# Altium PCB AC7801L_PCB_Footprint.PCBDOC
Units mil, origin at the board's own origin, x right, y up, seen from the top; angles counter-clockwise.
Board outline 634.92 x 634.92 mil, 2 copper layers (Top, Bottom), stack 12.7 mil thick; 1 components, 0 nets, 49 pads, 0 vias.
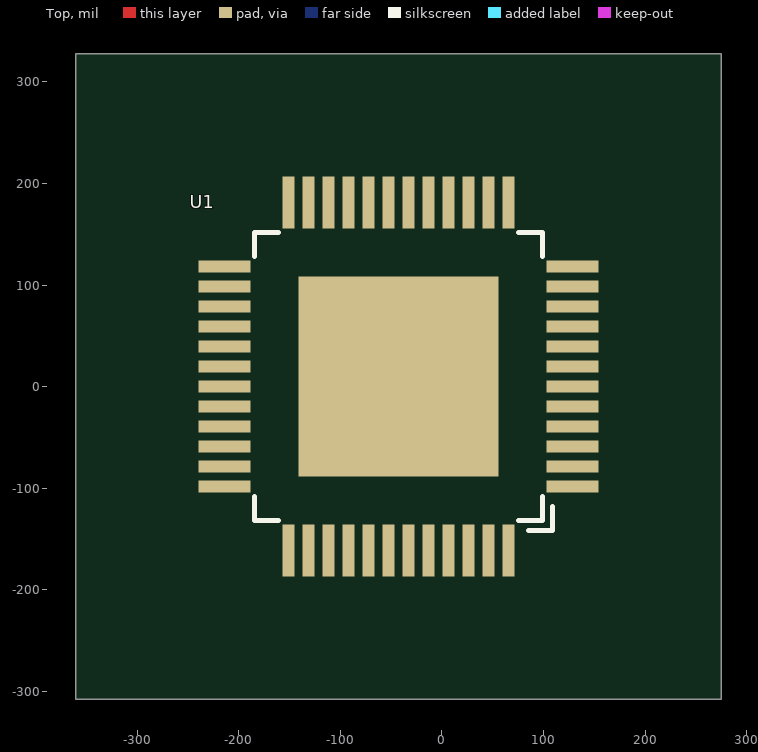
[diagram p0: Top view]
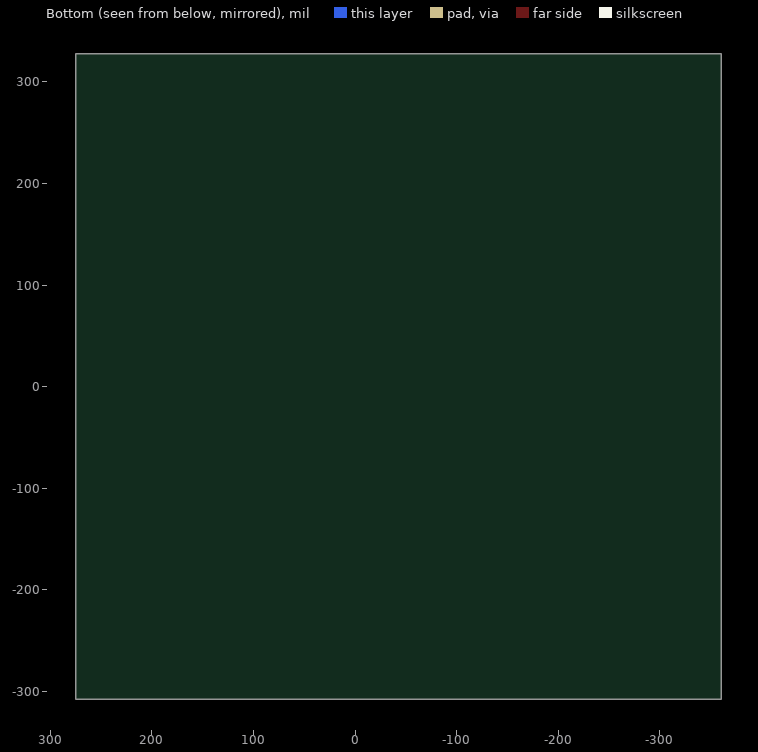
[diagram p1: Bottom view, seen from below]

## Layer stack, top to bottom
Top: signal copper 1.35
Dielectric: dielectric 10, FR-4, Dk 4.3
Bottom: signal copper 1.35

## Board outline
-360.21,-307.37 274.71,-307.37 274.71,327.55 -360.21,327.55

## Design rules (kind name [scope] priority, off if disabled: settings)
Clearance "'Default' PADS rule_18" [All] p1: gap=6
Clearance "'Default' PADS rule_15" [IsVia vs IsVia] p2: gap=6
ComponentClearance "'Default' PADS rule_12" [All] p1: gap=6 collisioncheckmode=3 verticalgap=10 showdistances=FALSE
FlightTimeFalling "'Default' PADS rule_10" [All] p1: maximum=10.00
FlightTimeRising "'Default' PADS rule_9" [All] p1: maximum=10.00
Length "'Default' PADS rule_5" [All] p1: maxlimit=50000 minlimit=0
MatchedLengths "'Default' PADS rule_11" [InNetClass('All Nets')] p1: tolerance=200 checknetsindiffpair=TRUE checkdiffpairvsdiffpair=TRUE checkothers=TRUE
MaxMinImpedance "'Default' PADS rule_8" [All] p1: minimum=50.00 maximum=150.0
ParallelSegment "'Default' PADS rule_7" [All] p1: limit=1000 gap=200
ParallelSegment "'Default' PADS rule_6" [All] p2: limit=1000 gap=200
PlaneClearance "'Default' PADS rule_14" [All] p1: clearance=6
PlaneConnect "Power Plane Connect Style - from global settings" [All] p1: planeconnectstyle=Relief reliefexpansion=20 reliefentries=2 reliefconductorwidth=15 reliefairgap=10
PolygonConnect [All] p1: connectstyle=Relief reliefconductorwidth=10 reliefentries=4 polygonreliefangle="90 Angle"
RoutingLayers "'Default' PADS rule_3" [All] p1: top layer_v5=TRUE bottom layer_v5=TRUE
RoutingPriority "'Default' PADS rule_2" [All] p1: routingpriority=3
RoutingTopology "'Default' PADS rule" [All] p1: topology=Shortest
RoutingVias "'Default' PADS rule_4" [All] p1: holewidth=37 width=55 viastyle="Through Hole" minholewidth=37 minwidth=55 maxholewidth=37 maxwidth=55
SMDToCorner "'Default' PADS rule_16" [All] p1: distance=60000
SMDToPlane "'Default' PADS rule_17" [All] p1: distance=60000
SilkscreenOverComponentPads [All] p1: minsilkscreentomaskgap=10
SolderMaskExpansion [All] p1: expansion=4
TestPointUsage [All] p1: valid=0 allowmultiple=FALSE
Testpoint [All] p1: side=15 testpointundercomponent=TRUE minsize=40 maxsize=100 preferedsize=60 minholesize=0 maxholesize=40 preferedholesize=32 testpointgrid=1 style=1023 order=0-112345678
Width "'Default' PADS rule_13" [All] p1: maxlimit=12 minlimit=12 preferedwidth=12
17 further rules are at their usual default settings.

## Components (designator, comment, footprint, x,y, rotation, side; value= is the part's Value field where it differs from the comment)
U1 "AC79013FDLA/LQFP48/SMD/P0.5/7X7" AC79013FDLA/LQFP48/SMD/P0.5/7X7 -42.75,10.09 r90 top

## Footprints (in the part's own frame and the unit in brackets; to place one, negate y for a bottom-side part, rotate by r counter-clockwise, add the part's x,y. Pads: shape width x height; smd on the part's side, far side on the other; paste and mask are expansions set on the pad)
AC79013FDLA/LQFP48/SMD/P0.5/7X7 [mm]
  rect 0.3x1.3 smd: 1(-2.75,-4.35) 2(-2.25,-4.35) 3(-1.75,-4.35) 4(-1.25,-4.35) 5(-0.75,-4.35) 6(-0.25,-4.35) 7(0.25,-4.35) 8(0.75,-4.35) 9(1.25,-4.35) 10(1.75,-4.35) 11(2.25,-4.35) 12(2.75,-4.35) 25(2.75,4.35) 26(2.25,4.35) 27(1.75,4.35) 28(1.25,4.35) 29(0.75,4.35) 30(0.25,4.35) 31(-0.25,4.35) 32(-0.75,4.35) 33(-1.25,4.35) 34(-1.75,4.35) 35(-2.25,4.35) 36(-2.75,4.35)
  rect 1.3x0.3 smd: 13(4.35,-2.75) 14(4.35,-2.25) 15(4.35,-1.75) 16(4.35,-1.25) 17(4.35,-0.75) 18(4.35,-0.25) 19(4.35,0.25) 20(4.35,0.75) 21(4.35,1.25) 22(4.35,1.75) 23(4.35,2.25) 24(4.35,2.75) 37(-4.35,2.75) 38(-4.35,2.25) 39(-4.35,1.75) 40(-4.35,1.25) 41(-4.35,0.75) 42(-4.35,0.25) 43(-4.35,-0.25) 44(-4.35,-0.75) 45(-4.35,-1.25) 46(-4.35,-1.75) 47(-4.35,-2.25) 48(-4.35,-2.75)
  rect 5x5 smd: 49(0,0)
  silkscreen extent -3.85,-3.85 3.6,3.6

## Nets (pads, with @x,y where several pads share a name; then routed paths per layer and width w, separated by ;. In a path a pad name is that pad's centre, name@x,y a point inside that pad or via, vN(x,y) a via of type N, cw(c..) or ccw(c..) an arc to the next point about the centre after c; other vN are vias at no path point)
pads on no net: U1.1 U1.2 U1.3 U1.4 U1.5 U1.6 U1.7 U1.8 U1.9 U1.10 U1.11 U1.12 U1.13 U1.14 U1.15 U1.16 U1.17 U1.18 U1.19 U1.20 U1.21 U1.22 U1.23 U1.24 U1.25 U1.26 U1.27 U1.28 U1.29 U1.30 U1.31 U1.32 U1.33 U1.34 U1.35 U1.36 U1.37 U1.38 U1.39 U1.40 U1.41 U1.42 U1.43 U1.44 U1.45 U1.46 U1.47 U1.48 U1.49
